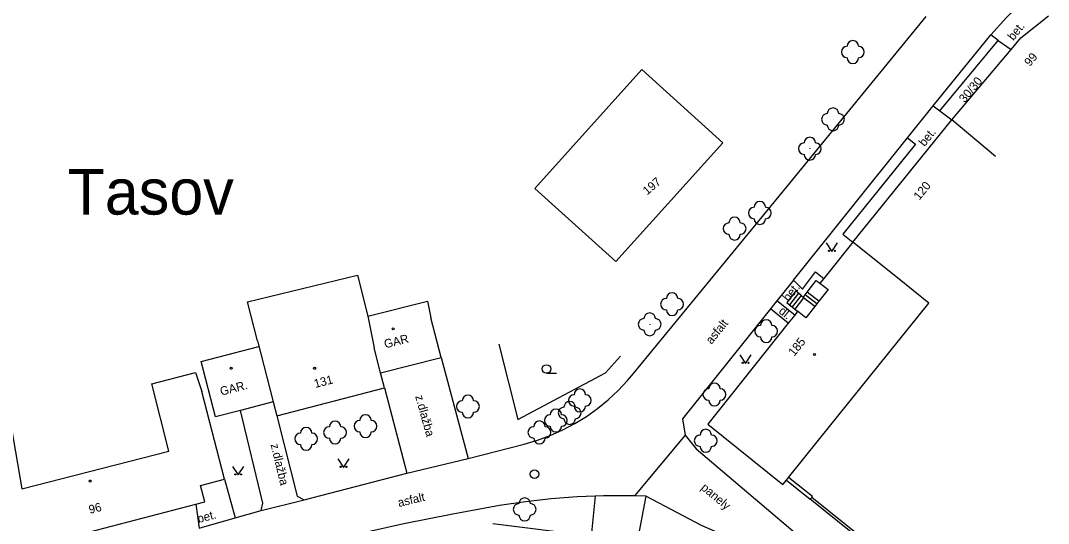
# Model space of a CAD drawing. Extents: x -544674 to -541478, y -1199076 to -1195527.
# Drawn here: x -542101.8 to -542011.8, y -1198883.1 to -1198839.1 of the extents above; entities that cross this region are included whole.
import ezdxf

# ---------------------------------------------------------------- set-up
doc = ezdxf.new("R2010")
doc.units = 0
for name, color, linetype in [('BUDOVY_MĚŘ', 7, 'Continuous'), ('BUDOVY_NEMĚŘ', 7, 'Continuous'), ('MAP_ZN_BP', 7, 'Continuous'), ('NÁZVY_SÍDEL_JEDNOTKY', 7, 'Continuous'), ('POMOC_POPIS', 7, 'Continuous'), ('ROZHRANÍ_PLOCH', 7, 'Continuous'), ('ZELEŇ', 7, 'Continuous'), ('ZN_BUDOV', 7, 'Continuous'), ('ZN_DOPLŇKOVÉ', 7, 'Continuous'), ('ZN_KULTUR', 7, 'Continuous'), ('Č_POPIS_ORIENT', 7, 'Continuous')]:
    doc.layers.add(name, color=color, linetype=linetype)

msp = doc.modelspace()

# ---------------------------------------------------------------- linework, layer by layer
at = {"layer": 'BUDOVY_MĚŘ'}
for points in [[(-542015.03, -1198841.61), (-542014.17, -1198840.59), (-542011.76, -1198838.67)], [(-542020.23, -1198847.76), (-542015.03, -1198841.61)], [(-542028.9, -1198858.48), (-542020.23, -1198847.76)], [(-542016.41, -1198850.99), (-542020.23, -1198847.76)], [(-542028.9, -1198858.48), (-542031.43, -1198861.65)], [(-542024.99, -1198861.6), (-542028.9, -1198858.48)], [(-542031.43, -1198861.65), (-542031.78, -1198862.08)], [(-542031.78, -1198862.08), (-542031.07, -1198862.63), (-542031.87, -1198863.65)], [(-542032.23, -1198864.12), (-542033, -1198865.11), (-542033.73, -1198864.53)], [(-542032.05, -1198863.88), (-542032.23, -1198864.12)], [(-542031.87, -1198863.65), (-542032.05, -1198863.88)], [(-542064.97, -1198868.57), (-542065.85, -1198865.09)], [(-542033.99, -1198864.86), (-542034.55, -1198865.56)], [(-542033.73, -1198864.53), (-542033.99, -1198864.86)], [(-542034.55, -1198865.56), (-542041.6, -1198874.4), (-542035.03, -1198879.69), (-542034.72, -1198879.3)], [(-542081.05, -1198867.12), (-542079.67, -1198872.46)], [(-542070.26, -1198869.91), (-542070.82, -1198867.74)], [(-542082.53, -1198873.2), (-542084.72, -1198873.76), (-542085.97, -1198868.92)], [(-542070.26, -1198869.91), (-542064.97, -1198868.57)], [(-542069.92, -1198871.23), (-542070.26, -1198869.91)], [(-542083.93, -1198879.23), (-542085.93, -1198871.56)], [(-542079.36, -1198873.67), (-542069.92, -1198871.23)], [(-542079.67, -1198872.46), (-542082.53, -1198873.2)], [(-542079.67, -1198872.46), (-542079.36, -1198873.67)], [(-542034.53, -1198879.07), (-542031.89, -1198875.8)], [(-542086.46, -1198881.41), (-542085.66, -1198881.2), (-542086.03, -1198879.78), (-542083.93, -1198879.23)], [(-542034.72, -1198879.3), (-542034.53, -1198879.07)], [(-542099.89, -1198884.91), (-542086.46, -1198881.41)]]:
    msp.add_lwpolyline(points, dxfattribs=at)
at = {"layer": 'BUDOVY_NEMĚŘ'}
for points in [[(-542040.29, -1198849.78), (-542047.39, -1198843.37), (-542056.76, -1198853.77), (-542049.65, -1198860.18)], [(-542049.65, -1198860.18), (-542040.29, -1198849.78)], [(-542081.05, -1198867.12), (-542081.93, -1198863.7), (-542072.28, -1198861.36), (-542071.39, -1198864.95)], [(-542022.23, -1198863.83), (-542024.99, -1198861.6)], [(-542071.39, -1198864.95), (-542066.14, -1198863.65), (-542065.85, -1198865.09)], [(-542031.89, -1198875.8), (-542022.23, -1198863.83)], [(-542071.39, -1198864.95), (-542070.82, -1198867.74)], [(-542085.97, -1198868.92), (-542080.92, -1198867.62)], [(-542106.32, -1198874.21), (-542102.79, -1198873.6), (-542101.68, -1198880.06), (-542088.8, -1198876.78), (-542090.31, -1198870.87), (-542086.47, -1198869.89), (-542085.93, -1198871.56)]]:
    msp.add_lwpolyline(points, dxfattribs=at)
at = {"layer": 'MAP_ZN_BP'}
for radius in [0.375, 0.0005]:
    msp.add_circle((-542056.78, -1198878.791), radius, dxfattribs=at)
at = {"layer": 'ROZHRANÍ_PLOCH'}
for points in [[(-542016.81, -1198840.31), (-542015.44, -1198838.81), (-542014.01, -1198837.37), (-542013.36, -1198836.75)], [(-542062.6, -1198877.42), (-542057.68, -1198876.15), (-542056.53, -1198875.81), (-542055.4, -1198875.4), (-542054.31, -1198874.92), (-542053.25, -1198874.36), (-542052.22, -1198873.73), (-542051.25, -1198873.04), (-542050.32, -1198872.28), (-542049.44, -1198871.46), (-542048.62, -1198870.59), (-542048.11, -1198869.98), (-542034.68, -1198853.63), (-542022.48, -1198838.71)], [(-542021.86, -1198846.55), (-542016.81, -1198840.31)], [(-542021.28, -1198846.98), (-542016.16, -1198840.82)], [(-542016.16, -1198840.82), (-542016.81, -1198840.31)], [(-542016.16, -1198840.82), (-542015.03, -1198841.61)], [(-542024.1, -1198849.35), (-542021.86, -1198846.55)], [(-542021.86, -1198846.55), (-542021.28, -1198846.98)], [(-542021.28, -1198846.98), (-542020.23, -1198847.76)], [(-542034.08, -1198861.81), (-542024.1, -1198849.35)], [(-542024.1, -1198849.35), (-542023.4, -1198849.9), (-542029.77, -1198857.78), (-542028.9, -1198858.48)], [(-542034.08, -1198861.81), (-542033.3, -1198862.58), (-542032.16, -1198861.06), (-542031.43, -1198861.65)], [(-542034.08, -1198861.81), (-542035.56, -1198863.6)], [(-542032.89, -1198862.85), (-542032.1, -1198861.83), (-542031.78, -1198862.08)], [(-542033.64, -1198862.93), (-542033.85, -1198862.71), (-542034.68, -1198863.77), (-542034.44, -1198863.96)], [(-542033.64, -1198862.93), (-542034.44, -1198863.96)], [(-542033.43, -1198863.15), (-542034.21, -1198864.14)], [(-542033.21, -1198863.36), (-542033.98, -1198864.33)], [(-542033.43, -1198863.15), (-542033.64, -1198862.93)], [(-542033.26, -1198863.32), (-542033.43, -1198863.15)], [(-542033.26, -1198863.32), (-542033.07, -1198863.08)], [(-542033.21, -1198863.36), (-542033.26, -1198863.32)], [(-542032.23, -1198864.12), (-542033.21, -1198863.36)], [(-542033.07, -1198863.08), (-542032.89, -1198862.85)], [(-542032.05, -1198863.88), (-542033.07, -1198863.08)], [(-542031.87, -1198863.65), (-542032.89, -1198862.85)], [(-542036.12, -1198864.3), (-542043.83, -1198873.95), (-542043.57, -1198875.36)], [(-542035.56, -1198863.6), (-542036.12, -1198864.3)], [(-542034.55, -1198865.56), (-542036.12, -1198864.3)], [(-542033.99, -1198864.86), (-542035.56, -1198863.6)], [(-542034.44, -1198863.96), (-542034.21, -1198864.14)], [(-542034.21, -1198864.14), (-542033.98, -1198864.33)], [(-542033.98, -1198864.33), (-542033.73, -1198864.53)], [(-542064.97, -1198868.57), (-542062.6, -1198877.42)], [(-542069.92, -1198871.23), (-542067.96, -1198878.71)], [(-542080.73, -1198881.96), (-542080.57, -1198881.32), (-542082.53, -1198873.2)], [(-542079.36, -1198873.67), (-542077.56, -1198880.72), (-542076.96, -1198881.05)], [(-542043.57, -1198875.36), (-542048.01, -1198880.69)], [(-542043.57, -1198875.36), (-542042.62, -1198876.58), (-542033.2, -1198884.57)], [(-542067.96, -1198878.71), (-542062.6, -1198877.42)], [(-542076.96, -1198881.05), (-542067.96, -1198878.71)], [(-542083.93, -1198879.23), (-542082.99, -1198882.62)], [(-542048.01, -1198880.69), (-542048.46, -1198880.68), (-542050.74, -1198880.69), (-542051.48, -1198880.72)], [(-542046.99, -1198880.72), (-542048.01, -1198880.69)], [(-542086.46, -1198881.41), (-542086.14, -1198883.53)], [(-542080.73, -1198881.96), (-542076.96, -1198881.05)], [(-542051.48, -1198880.72), (-542053.03, -1198880.78), (-542055.31, -1198880.95), (-542057.58, -1198881.2), (-542059.84, -1198881.53), (-542063.92, -1198882.28), (-542068.23, -1198883.15), (-542072.52, -1198884.1), (-542073.92, -1198884.4)], [(-542051.48, -1198880.72), (-542051.83, -1198884.21), (-542060.43, -1198883.15)], [(-542037.77, -1198887.26), (-542047.78, -1198884.87), (-542046.99, -1198880.72)], [(-542046.99, -1198880.72), (-542042.19, -1198883.26), (-542038.36, -1198884.91)], [(-542082.99, -1198882.62), (-542080.73, -1198881.96)], [(-542086.14, -1198883.53), (-542082.99, -1198882.62)]]:
    msp.add_lwpolyline(points, dxfattribs=at)
at = {"layer": 'ZELEŇ'}
for centre in [(-542028.89, -1198841.83), (-542030.63, -1198847.72), (-542032.66, -1198850.29), (-542037.04, -1198855.92), (-542039.25, -1198857.29), (-542044.73, -1198863.91), (-542046.69, -1198865.67), (-542036.48, -1198866.27), (-542052.81, -1198872.33), (-542041.02, -1198871.81), (-542062.61, -1198872.86), (-542053.7, -1198873.43), (-542054.91, -1198874.09), (-542074.25, -1198875.14), (-542071.58, -1198874.59), (-542056.35, -1198875.13), (-542076.78, -1198875.69), (-542041.78, -1198875.86), (-542057.64, -1198881.87)]:
    msp.add_circle(centre, 0.0005, dxfattribs=at)
for centre, start, end in [((-542028.89, -1198841.33), 0, 179.99999), ((-542029.39, -1198841.83), 89.99999, 269.99999), ((-542028.39, -1198841.83), 270, 89.99999), ((-542028.89, -1198842.33), 179.99999, 359.99999), ((-542031.13, -1198847.72), 89.99999, 269.99999), ((-542030.63, -1198847.22), 0, 179.99999), ((-542030.13, -1198847.72), 270, 89.99999), ((-542030.63, -1198848.22), 179.99999, 359.99999), ((-542033.16, -1198850.29), 89.99999, 269.99999), ((-542032.66, -1198849.79), 0, 179.99999), ((-542032.16, -1198850.29), 270, 89.99999), ((-542032.66, -1198850.79), 179.99999, 359.99999), ((-542037.54, -1198855.92), 89.99999, 269.99999), ((-542037.04, -1198855.42), 0, 179.99999), ((-542036.54, -1198855.92), 270, 89.99999), ((-542039.25, -1198856.79), 0, 179.99999), ((-542039.75, -1198857.29), 89.99999, 269.99999), ((-542038.75, -1198857.29), 270, 89.99999), ((-542037.04, -1198856.42), 179.99999, 359.99999), ((-542039.25, -1198857.79), 179.99999, 359.99999), ((-542045.23, -1198863.91), 89.99999, 269.99999), ((-542044.73, -1198863.41), 0, 179.99999), ((-542044.23, -1198863.91), 270, 89.99999), ((-542044.73, -1198864.41), 179.99999, 359.99999), ((-542047.19, -1198865.67), 89.99999, 269.99999), ((-542046.69, -1198865.17), 0, 179.99999), ((-542046.19, -1198865.67), 270, 89.99999), ((-542036.48, -1198865.77), 0, 179.99999), ((-542046.69, -1198866.17), 179.99999, 359.99999), ((-542036.98, -1198866.27), 89.99999, 269.99999), ((-542035.98, -1198866.27), 270, 89.99999), ((-542036.48, -1198866.77), 179.99999, 359.99999), ((-542052.81, -1198871.83), 0, 179.99999), ((-542041.52, -1198871.81), 89.99999, 269.99999), ((-542041.02, -1198871.31), 0, 179.99999), ((-542040.52, -1198871.81), 270, 89.99999), ((-542063.11, -1198872.86), 89.99999, 269.99999), ((-542062.61, -1198872.36), 0, 179.99999), ((-542062.11, -1198872.86), 270, 89.99999), ((-542053.7, -1198872.93), 0, 179.99999), ((-542053.31, -1198872.33), 89.99999, 269.99999), ((-542052.31, -1198872.33), 270, 89.99999), ((-542041.02, -1198872.31), 179.99999, 359.99999), ((-542062.61, -1198873.36), 179.99999, 359.99999), ((-542054.91, -1198873.59), 0, 179.99999), ((-542054.2, -1198873.43), 89.99999, 269.99999), ((-542052.81, -1198872.83), 179.99999, 359.99999), ((-542053.2, -1198873.43), 270, 89.99999), ((-542074.25, -1198874.64), 0, 179.99999), ((-542072.08, -1198874.59), 89.99999, 269.99999), ((-542071.58, -1198874.09), 0, 179.99999), ((-542071.08, -1198874.59), 270, 89.99999), ((-542056.35, -1198874.63), 0, 179.99999), ((-542055.41, -1198874.09), 89.99999, 269.99999), ((-542054.41, -1198874.09), 270, 89.99999), ((-542053.7, -1198873.93), 179.99999, 359.99999), ((-542077.28, -1198875.69), 89.99999, 269.99999), ((-542076.78, -1198875.19), 0, 179.99999), ((-542076.28, -1198875.69), 270, 89.99999), ((-542074.75, -1198875.14), 89.99999, 269.99999), ((-542073.75, -1198875.14), 270, 89.99999), ((-542071.58, -1198875.09), 179.99999, 359.99999), ((-542056.85, -1198875.13), 89.99999, 269.99999), ((-542055.85, -1198875.13), 270, 89.99999), ((-542054.91, -1198874.59), 179.99999, 359.99999), ((-542041.78, -1198875.36), 0, 179.99999), ((-542076.78, -1198876.19), 179.99999, 359.99999), ((-542074.25, -1198875.64), 179.99999, 359.99999), ((-542056.35, -1198875.63), 179.99999, 359.99999), ((-542042.28, -1198875.86), 89.99999, 269.99999), ((-542041.28, -1198875.86), 270, 89.99999), ((-542041.78, -1198876.36), 179.99999, 359.99999), ((-542058.14, -1198881.87), 89.99999, 269.99999), ((-542057.64, -1198881.37), 0, 179.99999), ((-542057.14, -1198881.87), 270, 89.99999), ((-542057.64, -1198882.37), 179.99999, 359.99999)]:
    msp.add_arc(centre, 0.5, start, end, dxfattribs=at)
at = {"layer": 'ZN_BUDOV'}
for centre in [(-542069.15, -1198866.07), (-542032.25, -1198868.31), (-542083.36, -1198869.52), (-542076.04, -1198869.52), (-542095.7, -1198879.39)]:
    msp.add_circle(centre, 0.0875, dxfattribs=at)
at = {"layer": 'ZN_DOPLŇKOVÉ'}
for points in [[(-542059.89, -1198867.42), (-542058.24, -1198874.01), (-542050.57, -1198869.91)], [(-542050.57, -1198869.91), (-542049.25, -1198868.46)], [(-542034.72, -1198879.3), (-542032.63, -1198880.98)], [(-542032.5, -1198880.83), (-542032.44, -1198880.75), (-542034.53, -1198879.07)], [(-542032.63, -1198880.98), (-542032.5, -1198880.83)], [(-542025.3, -1198886.87), (-542032.63, -1198880.98)], [(-542025.3, -1198886.87), (-542025.18, -1198886.71), (-542032.5, -1198880.83)]]:
    msp.add_lwpolyline(points, dxfattribs=at)
at = {"layer": 'ZN_KULTUR'}
msp.add_line((-542055.73, -1198869.955), (-542054.855, -1198869.955), dxfattribs=at)
for points in [[(-542031.23, -1198858.54), (-542030.73, -1198859.29), (-542030.23, -1198858.54)], [(-542038.79, -1198868.34), (-542038.29, -1198869.09), (-542037.79, -1198868.34)], [(-542074.01, -1198877.45), (-542073.51, -1198878.2), (-542073.01, -1198877.45)], [(-542083.24, -1198878.11), (-542082.74, -1198878.86), (-542082.24, -1198878.11)]]:
    msp.add_lwpolyline(points, dxfattribs=at)
for centre, radius in [((-542030.98, -1198859.24), 0.05), ((-542030.48, -1198859.24), 0.05), ((-542038.54, -1198869.04), 0.05), ((-542038.04, -1198869.04), 0.05), ((-542055.73, -1198869.58), 0.375), ((-542082.99, -1198878.81), 0.05), ((-542082.49, -1198878.81), 0.05), ((-542073.76, -1198878.15), 0.05), ((-542073.26, -1198878.15), 0.05)]:
    msp.add_circle(centre, radius, dxfattribs=at)

# ---------------------------------------------------------------- texts
at = {"layer": 'NÁZVY_SÍDEL_JEDNOTKY'}
msp.add_text('Tasov', height=4, dxfattribs=at).set_placement((-542097.69, -1198856.06))
at = {"layer": 'POMOC_POPIS'}
for s, rotation, p in [('bet.', 51.30997, (-542014.83, -1198840.88)), ('30/30', 50.27, (-542019.1, -1198846.33)), ('bet.', 51.30997, (-542022.61, -1198850.16)), ('bet.', 50.79999, (-542034.53, -1198863.73)), ('dl.', 321.24999, (-542035.45, -1198864.62)), ('asfalt', 51.37002, (-542041.27, -1198867.47)), ('GAR', 14.18999, (-542069.85, -1198867.78)), ('GAR.', 14.48999, (-542084.22, -1198871.92)), ('z.dlažba', 285.67, (-542067.24, -1198871.97)), ('z.dlažba', 283.58999, (-542079.9, -1198876.2)), ('panely', 320.02999, (-542042.26, -1198880.07)), ('asfalt', 13.45998, (-542068.66, -1198881.67)), ('bet.', 14.54001, (-542086.21, -1198883.07))]:
    msp.add_text(s, height=0.75, rotation=rotation, dxfattribs=at).set_placement(p)
at = {"layer": 'Č_POPIS_ORIENT'}
for s, rotation, p in [('99', 49.8, (-542013.38, -1198843.14)), ('197', 40.00002, (-542046.91, -1198854.39)), ('120', 51.04, (-542023.07, -1198854.85)), ('185', 51.41998, (-542034.03, -1198868.52)), ('131', 14.48999, (-542075.99, -1198871.25)), ('96', 14.61999, (-542095.72, -1198882.27))]:
    msp.add_text(s, height=0.75, rotation=rotation, dxfattribs=at).set_placement(p)

doc.saveas('drawing.dxf')
